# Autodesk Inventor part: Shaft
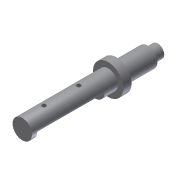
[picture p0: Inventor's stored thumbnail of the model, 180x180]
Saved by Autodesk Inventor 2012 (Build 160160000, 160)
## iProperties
Created: 2009-04
Part Number: Shaft
Document SubType Name: Modeling
Designer: Sham
Density: 1 g/cm^3
Material: Default
Mass: 759.603 g
Surface Area: 791.068 cm^2
Volume: 759.603 cm^3
Author: Sham
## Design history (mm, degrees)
sketch "Sketch1"
  geometry: C1 r 18.75 at (511.175, 103.188)
  constraints: 1 centre point
  dimensions: "d0" = 37.5 diameter of C1
extrude "Extrusion1" new body sketch "Sketch1" distance "d1" = 28.9; taper "d2" = 0 deg
sketch "Sketch2"
  geometry: C1 r 28 at (0, 0)
  constraints: 1 centre point
  dimensions: "d3" = 56 diameter of C1
extrude "Extrusion2" join sketch "Sketch2" distance "d4" = 89.8; taper "d5" = 0 deg
sketch "Sketch3"
  geometry: C1 r 43.6 at (0, 0)
  constraints: 1 centre point
  dimensions: "d6" = 87.2 diameter of C1
extrude "Extrusion3" join sketch "Sketch3" distance "d7" = 24; taper "d8" = 0 deg
sketch "Sketch4"
  geometry: C1 r 43.6 at (0, 0) reference; C2 r 28 at (0, 0)
  constraints: 1 centre point, 1 coincident
  dimensions: "d9" = 56 diameter of C2
extrude "Extrusion4" join sketch "Sketch4" distance "d10" = 247.1; taper "d11" = 0 deg
workplane "Work Plane1"
sketch "Sketch5"
  geometry: L1 (28, 0)-(-28, 0); C1 r 43.6 at (0, 0) reference; A1 r 28 centre (0, 0) between (-28, 0) and (28, 0)
  constraints: 2 end point, 2 point on circle, 1 centre point, 1 concentric, 1 horizontal
  dimensions: "d13" = 56 diameter of A1
extrude "Extrusion5" cut sketch "Sketch5" distance "d14" = 193.8; taper "d15" = 0 deg
hole "Hole1" diameter "d18" = 12.5; stored, may be unused: countersink angle "d22" = 90 deg, drill point angle "d24" = 118 deg; dims "d16" = 28, "d17" = 46.9, "d19" = 6, "d20" = 4, "d21" = 2, "d23" = 8
pattern_linear "Rectangular Pattern1" dims "d27" = 100
body "Solid1"
other parameters: "d12" = -15.1
